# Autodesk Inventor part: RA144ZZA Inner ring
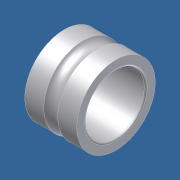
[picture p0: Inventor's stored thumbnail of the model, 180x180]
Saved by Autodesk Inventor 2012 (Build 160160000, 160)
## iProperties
Category: PARTsolutions
Created: 2011-07
Part Number: RA144ZZA Inner ring
Catalog Web Link: www.cadenas.de
Description: Six types ir - Inch system sizes
Document SubType Name: Modeling
Designer: PARTsolutions
Density: 1 g/cm^3
Material: Par défaut
NB: RA144ZZA Inner ring
NN: Six types ir
NT: Inch system sizes
NBSYN: RA144ZZA Inner ring
LINA: RA144ZZA Inner ring
SD: 3.175
D: 6.350
B: 2.380
B1: 2.779
D1: 7.52
D2: 7.52
C1: 0.58
C2: 0.79
R: 0.08
ORDER: RA144ZZA
CR: 284
COR: 96
CRF: 29
CORF: 10
LSG: 59000
LSO: 70000
MASS: 0.27
ORDER1: R144
WSS: RA144ZA
WDS: RA144ZZA
UTWF: FLR144
FORSS: FLRA144ZA
FORDS: FLRA144ZZA
DA1: 3.9
DA2: 4
DA: 5.5
RAS: 0.08
MASS1: 0.33
VERS: 3
X: 1.587
N: 9
O: 14.954
RB: 0.470
KT: DUMMY
SUPPLIER: NTN
ARTICLENO: RA144ZZA Inner ring
BOMINFO: RA144ZZA Inner ring
CREATOR: CADENAS GmbH
PSOL_IDENT_0: {\\10.0.0.251\ps_data\23d-libs\ntn\ball_roller_bearings\miniature_extra_small_bb\inch_system_sizes\i
PSOL_IDENT_1: ss_ir.prj},189 {VTYP=3D},{NB=RA144ZZA Inner ring},{LINA=RA144ZZA Inner ring},{NN=Six types ir},{DATE
PSOL_IDENT_2: =11.12.2007 08:48:22},{GEOMDATE=28.06.2007 13:01:00},{VERSION=},{LINEID=16080},{LINESUBID=-1},{WBVAR
PSOL_IDENT_3: =}  {NB=RA144ZZA Inner ring},{LINA=RA144ZZA Inner ring},{KT=DUMMY},{IDNR=},{SD=3.175},{D=6.350},{B=2
PSOL_IDENT_4: .380},{B1=2.779},{D1=7.52},{D2=7.52},{C1=0.58},{C2=0.79},{R=0.08},{ORDER=RA144ZZA},{CR=284},{COR=96}
PSOL_IDENT_5: ,{CRF=29},{CORF=10},{LSG=59000},{LSO=70000},{MASS=0.27},{ORDER1=R144},{WSS=RA144ZA},{WDS=RA144ZZA},{
PSOL_IDENT_6: UTWF=FLR144},{FORSS=FLRA144ZA},{FORDS=FLRA144ZZA},{DA1=3.9},{DA2=4},{DA=5.5},{RAS=0.08},{MASS1=0.33}
PSOL_IDENT_7: ,{VERS=3},{X=1.5875},{N=9},{O=14.95425},{RB=0.4699}
Title: RA144ZZA Inner ring
Author: Cadenas PARTsolutions
Comments: Inch system sizes
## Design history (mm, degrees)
sketch "Sketch_2"
  geometry: L1 (2.779, 0)-(0, 0); L2 (0, 2.096)-(0, 1.667); L3 (0.08, 1.587)-(2.699, 1.587); L4 (2.779, 1.667)-(2.779, 2.096); L5 (2.779, 2.096)-(1.763, 2.096); L6 (1.016, 2.096)-(0, 2.096); A1 r 0.08 centre (0.08, 1.668) between (0, 1.667) and (0.08, 1.587); A2 r 0.08 centre (2.699, 1.668) between (2.699, 1.587) and (2.779, 1.667); A3 r 0.47 centre (1.39, 2.381) between (1.016, 2.096) and (1.763, 2.096)
  constraints: 12 end point, 6 point on circle, 3 centre point
revolve "Revolution1" sketch "Sketch_2" stored, may be unused: angle "d0" = 360 deg
node "iss_ir_XY"
node "iss_ir_YZ"
node "iss_ir_ZX"
node "iss_ir_X"
node "iss_ir_Y"
node "iss_ir_Z"
node "iss_ir_Center"
node "Solide1"
node "Corps solides"
node "Corps surfaciques"
